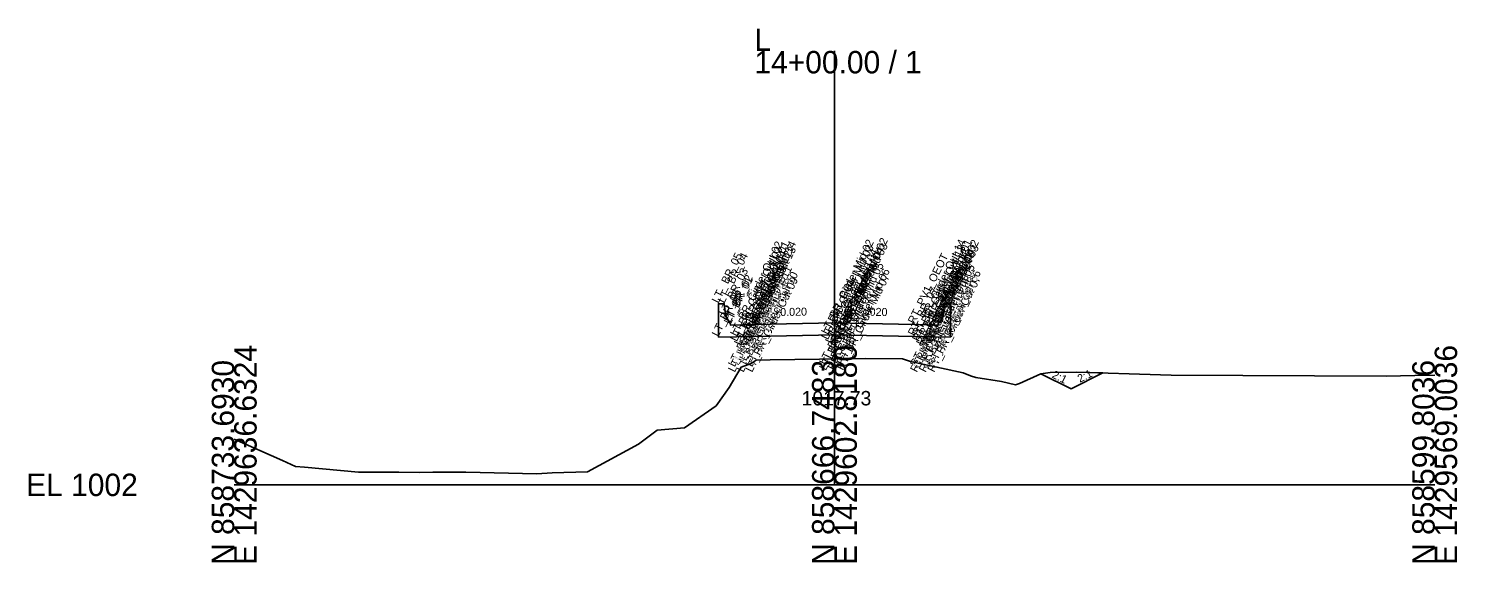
# Model space of a CAD drawing. Extents: x -26 to 176, y -10 to 13058.
# Drawn here: x -25.7 to 152.8, y 4990.3 to 5057 of the extents above; entities that cross this region are included whole.
import ezdxf

# ---------------------------------------------------------------- set-up
doc = ezdxf.new("R2010")
doc.units = 0
for name, color, linetype in [('Default', 7, 'Continuous'), ('Exist Cross Section Cell', 7, 'Continuous'), ('Exist XS Center Line Elevation Label', 7, 'Continuous'), ('Exist XS Ground Line', 7, 'Continuous'), ('Old_Level_50', 7, 'Continuous'), ('Prop CMT Concrete Structures', 7, 'Continuous'), ('Prop CMT Slope Grass', 7, 'Continuous'), ('Prop XS Dump Level', 7, 'Continuous'), ('Prop XS SE Text', 7, 'Continuous'), ('Prop XS Side Slope Text', 7, 'Continuous')]:
    doc.layers.add(name, color=color, linetype=linetype)

msp = doc.modelspace()

# ---------------------------------------------------------------- linework, layer by layer
at = {"layer": 'Exist Cross Section Cell'}
for p, q in [((75, 5000), (75, 5054.22)), ((0, 5000), (75, 5000)), ((75, 5000), (150, 5000))]:
    msp.add_line(p, q, dxfattribs=at)
at = {"layer": 'Exist XS Ground Line'}
msp.add_lwpolyline([(0, 5005.73), (6.02, 5003.05), (7.64, 5002.3), (8.79, 5002.22), (15.53, 5001.6), (20.58, 5001.57), (23.13, 5001.56), (24.82, 5001.58), (28.93, 5001.59), (37.81, 5001.39), (39.72, 5001.51), (44.15, 5001.64), (50.51, 5005.07), (52.85, 5006.83), (56.25, 5007.14), (60.2, 5009.88), (61.83, 5012.15), (63.34, 5014.71), (64.6, 5015.17), (65.23, 5015.6), (66.95, 5015.62), (73.15, 5015.71), (75, 5015.73), (78.87, 5015.79), (83.49, 5015.75), (84.51, 5015.41), (91.07, 5013.99), (91.98, 5013.62), (92.66, 5013.43), (95.86, 5012.93), (97.63, 5012.48), (98.11, 5012.68), (100.8, 5013.88), (101.94, 5014.06), (105.28, 5014.08), (115.76, 5013.76), (117.06, 5013.69), (143.93, 5013.58), (147.53, 5013.65), (150, 5013.69)], dxfattribs=at)
at = {"layer": 'Old_Level_50'}
for points in [[(105.28, 5014.08), (108.52, 5013.98), (104.56, 5012), (100.8, 5013.88), (101.94, 5014.06)], [(104.56, 5012), (100.8, 5013.88), (101.94, 5014.06), (105.28, 5014.08), (108.52, 5013.98)]]:
    msp.add_lwpolyline(points, close=True, dxfattribs=at)
at = {"layer": 'Prop CMT Concrete Structures'}
for points in [[(75, 5020.23), (65, 5020.03), (62, 5019.97), (61.99, 5020.22), (61.41, 5021.05), (61.24, 5022.63), (60.5, 5022.63), (60.5, 5018.44)], [(75, 5020.23), (85, 5020.03), (88, 5019.97), (88.01, 5020.22), (88.59, 5021.05), (88.76, 5022.63), (89.5, 5022.63), (89.5, 5018.44)], [(60.5, 5018.44), (65, 5018.53), (75, 5018.73)], [(75, 5018.73), (75, 5020.23)], [(75, 5018.73), (75, 5020.23)], [(89.5, 5018.44), (85, 5018.53), (75, 5018.73)]]:
    msp.add_lwpolyline(points, dxfattribs=at)
at = {"layer": 'Prop CMT Slope Grass'}
for q in [(100.8, 5013.88), (108.52, 5013.98)]:
    msp.add_line((104.56, 5012), q, dxfattribs=at)

# ---------------------------------------------------------------- texts
at = {"layer": 'Default'}
msp.add_text('-', height=0.0001, dxfattribs=at).set_placement((0, 5000))
at = {"layer": 'Exist Cross Section Cell'}
for s, p in [('L', (65, 5054.22)), ('14+00.00 / 1', (65, 5051.42)), ('EL 1002', (-26, 4998.6))]:
    msp.add_text(s, height=2.8, dxfattribs=at).set_placement(p)
for s, p in [('E 1429636.6324', (2.8, 4990)), ('E 1429602.8180', (77.8, 4990)), ('E 1429569.0036', (152.8, 4990)), ('N 858733.6930', (0, 4990)), ('N 858666.7483', (75, 4990)), ('N 858599.8036', (150, 4990))]:
    msp.add_text(s, height=2.8, rotation=90, dxfattribs=at).set_placement(p)
at = {"layer": 'Exist XS Center Line Elevation Label'}
msp.add_text('1017.73', height=1.8, dxfattribs=at).set_placement((70.9, 5009.93))
msp.add_text('1017.73', height=1.8, dxfattribs=at).set_placement((70.9, 5009.93))
msp.add_text('1017.73', height=1.8, dxfattribs=at).set_placement((70.9, 5009.93))
at = {"layer": 'Prop XS Dump Level'}
for s, p in [('LT_BR_Girder Out 02', (62.79, 5018.48)), ('LT_BR_Girder Out 03', (62.79, 5017.83)), ('LT_BR_Girder Out 04', (63.29, 5017.33)), ('LT_BR_Girder Out 01', (63.62, 5018.5)), ('LT_BR_Girder Out 12', (63.96, 5017.33)), ('LT_BR_Girder Out 14', (64.46, 5018.52)), ('LT_BR_Girder Out 13', (64.46, 5017.83)), ('LT_BR_Girder Mid 02', (74.17, 5018.71)), ('LT_BR_Girder Mid 03', (74.17, 5018.06)), ('LT_BR_Girder Mid 04', (74.67, 5017.56)), ('RT_BR_Girder Mid 04', (75.33, 5017.56)), ('RT_BR_Girder Mid 02', (75.83, 5018.71)), ('RT_BR_Girder Mid 03', (75.83, 5018.06)), ('RT_BR_Girder Out 14', (85.54, 5018.52)), ('RT_BR_Girder Out 13', (85.54, 5017.83)), ('RT_BR_Girder Out 12', (86.04, 5017.33)), ('RT_BR_Girder Out 01', (86.38, 5018.5)), ('RT_BR_Girder Out 04', (86.71, 5017.33)), ('RT_BR_Girder Out 02', (87.21, 5018.48)), ('RT_BR_Girder Out 03', (87.21, 5017.83)), ('LT_ BR_05', (60.5, 5022.63)), ('LT_ BR_04', (61.24, 5022.63)), ('LT_PV1_OEOT', (65, 5020.03)), ('LT_BR_Girder Mid 05', (74.67, 5015.64)), ('RT_BR_Girder Mid 05', (75.33, 5015.64)), ('RT_PV1_OEOT', (85, 5020.03)), ('RT_BR_Girder Out 05', (86.71, 5015.42)), ('RT_ BR_04', (88.76, 5022.63)), ('RT_ BR_05', (89.5, 5022.63)), ('LT_BR_03', (61.41, 5021.05)), ('LT_BR_02', (61.99, 5020.22)), ('LT_BR_01', (62, 5019.97)), ('LT_BR_Girder Out 06', (62.54, 5014.67)), ('LT_BR_Girder Out 07', (62.54, 5014)), ('LT_BR_Girder Out 05', (63.29, 5015.42)), ('LT_BR_Girder Out 08', (63.62, 5014)), ('LT_BR_Girder Out 11', (63.96, 5015.42)), ('LT_BR_Girder Out 10', (64.71, 5014.67)), ('LT_BR_Girder Out 09', (64.71, 5014)), ('LT_BR_Girder Mid 06', (73.92, 5014.89)), ('LT_BR_Girder Mid 07', (73.92, 5014.23)), ('RT_BR_Girder Mid 06', (76.08, 5014.89)), ('RT_BR_Girder Mid 07', (76.08, 5014.23)), ('RT_BR_Girder Out 10', (85.29, 5014.67)), ('RT_BR_Girder Out 09', (85.29, 5014)), ('RT_BR_Girder Out 11', (86.04, 5015.42)), ('RT_BR_Girder Out 08', (86.38, 5014)), ('RT_BR_Girder Out 06', (87.46, 5014.67)), ('RT_BR_Girder Out 07', (87.46, 5014)), ('RT_BR_01', (88, 5019.97)), ('RT_BR_02', (88.01, 5020.22)), ('RT_BR_03', (88.59, 5021.05)), ('LT_BR_06', (60.5, 5018.44)), ('LT_BR_07', (65, 5018.53)), ('PV1_PGL', (75, 5020.23)), ('BR_Girder Mid 08', (75, 5014.23)), ('RT_BR_07', (85, 5018.53)), ('RT_BR_06', (89.5, 5018.44)), ('BR_PGL', (75, 5018.73))]:
    msp.add_text(s, height=1, rotation=63.5833, dxfattribs=at).set_placement(p)
at = {"layer": 'Prop XS SE Text'}
for rotation, p in [(1.1458, (68.23, 5021.09)), (358.8542, (78.27, 5021.16))]:
    msp.add_text('0.020', height=1, rotation=rotation, dxfattribs=at).set_placement(p)
at = {"layer": 'Prop XS Side Slope Text'}
for rotation, p in [(333.4349, (102.09, 5013.44)), (26.5651, (105.67, 5012.75))]:
    msp.add_text('2:1', height=1, rotation=rotation, dxfattribs=at).set_placement(p)

doc.saveas('drawing.dxf')
